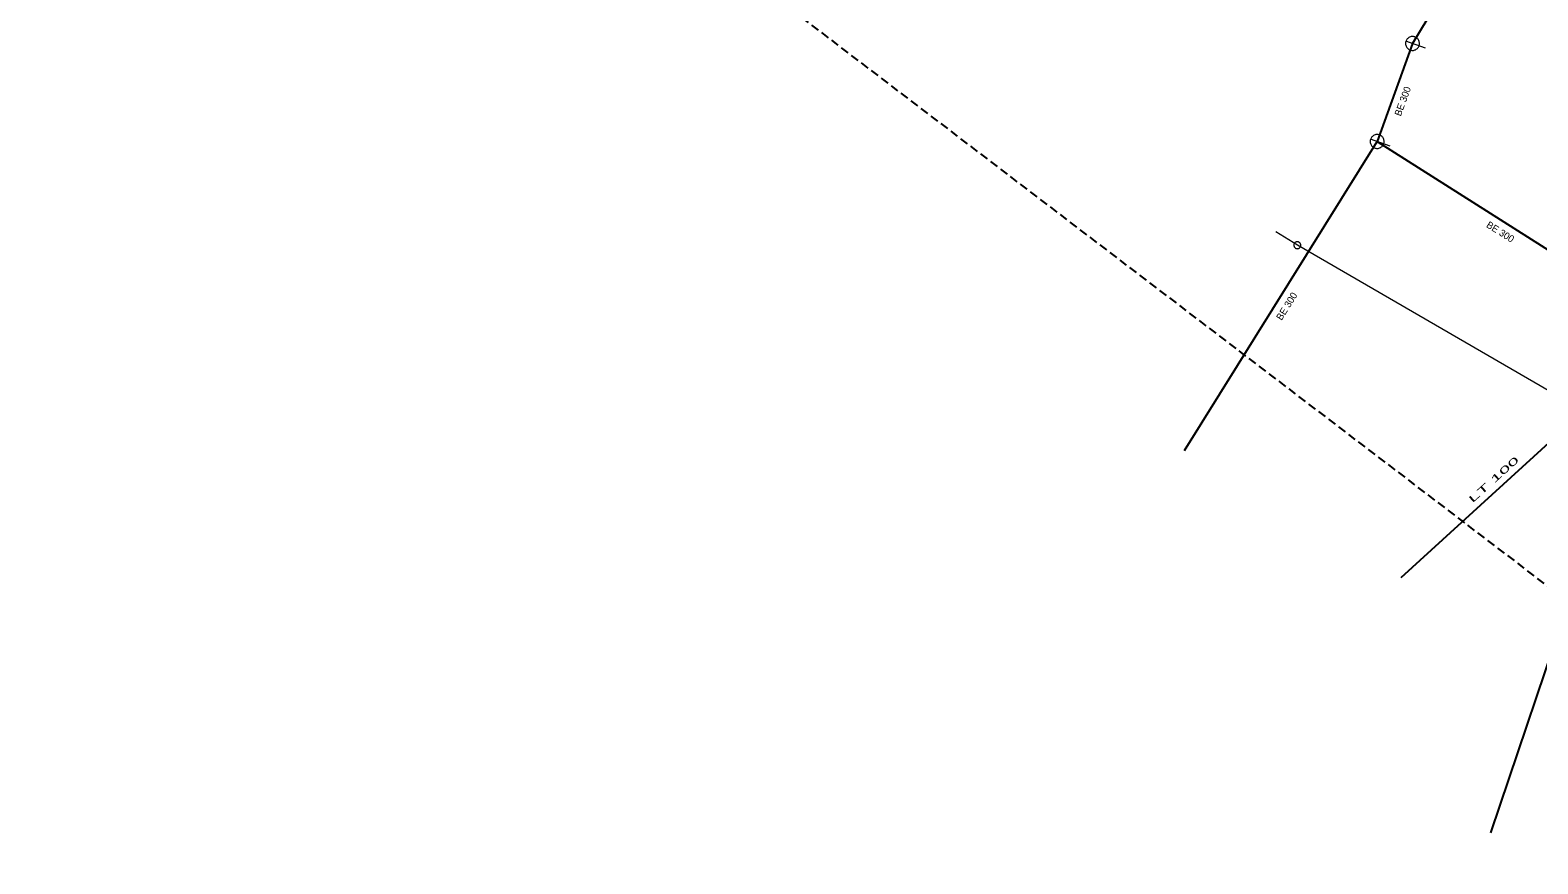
# Model space of a CAD drawing. Extents: x -791337 to -790755, y -988454 to -987923.
# Drawn here: x -791331.5 to -791114.4, y -988280.4 to -988160.4 of the extents above; entities that cross this region are included whole.
import ezdxf

# ---------------------------------------------------------------- set-up
doc = ezdxf.new("R2010")
doc.units = 0
doc.header["$LTSCALE"] = 0.4
doc.linetypes.add('MEDIUM_DASHED', pattern=[4.5, 3, -1.5])
for name, color, linetype, lineweight in [('1', 7, 'Continuous', 13), ('13', 7, 'Continuous', 13), ('14', 7, 'Continuous', 25), ('17', 7, 'Continuous', 25), ('22', 7, 'Continuous', 13), ('23', 7, 'Continuous', 13), ('63', 7, 'MEDIUM_DASHED', 25)]:
    doc.layers.add(name, color=color, linetype=linetype, lineweight=lineweight)

msp = doc.modelspace()

# ---------------------------------------------------------------- linework, layer by layer
at = {"layer": '13'}
msp.add_line((-791149.015, -988191.33), (-791152.136, -988189.414), dxfattribs=at)
msp.add_lwpolyline([(-791107.868, -988215.265), (-791108.388, -988214.918), (-791149.015, -988191.33)], dxfattribs=at)
at = {"layer": '14'}
for p, q in [((-791124.854, -988149.635), (-791132.46, -988162.294)), ((-791132.46, -988162.294), (-791137.55, -988176.404)), ((-791165.269, -988220.905), (-791137.55, -988176.404)), ((-791137.55, -988176.404), (-791099.119, -988200.823)), ((-791106.431, -988231.991), (-791121.225, -988275.947))]:
    msp.add_line(p, q, dxfattribs=at)
at = {"layer": '17'}
msp.add_lwpolyline([(-791134.081, -988239.197), (-791107.868, -988215.265), (-791103.719, -988211.362), (-791100.587, -988208.045)], dxfattribs=at)
at = {"layer": '22'}
for p, q in [((-791130.578, -988162.972), (-791133.4, -988161.954)), ((-791135.668, -988177.082), (-791138.49, -988176.064))]:
    msp.add_line(p, q, dxfattribs=at)
for points in [[(-791132.12, -988161.353), (-791132.224, -988161.322), (-791132.332, -988161.302), (-791132.442, -988161.294), (-791132.55, -988161.298), (-791132.659, -988161.314), (-791132.765, -988161.341), (-791132.868, -988161.381), (-791132.964, -988161.431), (-791133.056, -988161.491), (-791133.14, -988161.561), (-791133.216, -988161.64), (-791133.283, -988161.728), (-791133.34, -988161.821), (-791133.386, -988161.92), (-791133.422, -988162.024), (-791133.445, -988162.13), (-791133.458, -988162.24), (-791133.458, -988162.349), (-791133.445, -988162.458), (-791133.422, -988162.564), (-791133.386, -988162.668), (-791133.34, -988162.767), (-791133.282, -988162.861), (-791133.216, -988162.948), (-791133.14, -988163.026), (-791133.056, -988163.096), (-791132.964, -988163.157), (-791132.867, -988163.206), (-791132.764, -988163.246), (-791132.658, -988163.273), (-791132.55, -988163.29), (-791132.441, -988163.293), (-791132.332, -988163.286), (-791132.224, -988163.266), (-791132.119, -988163.234), (-791132.019, -988163.191), (-791131.923, -988163.138), (-791131.834, -988163.074), (-791131.752, -988163.001), (-791131.679, -988162.919), (-791131.615, -988162.831), (-791131.562, -988162.735), (-791131.519, -988162.634), (-791131.487, -988162.529), (-791131.468, -988162.422), (-791131.459, -988162.313), (-791131.463, -988162.203), (-791131.479, -988162.094), (-791131.507, -988161.989), (-791131.546, -988161.886), (-791131.595, -988161.789), (-791131.656, -988161.698), (-791131.726, -988161.613), (-791131.805, -988161.538), (-791131.891, -988161.471), (-791131.985, -988161.413), (-791132.084, -988161.367)], [(-791137.21, -988175.463), (-791137.314, -988175.432), (-791137.422, -988175.412), (-791137.532, -988175.404), (-791137.64, -988175.408), (-791137.749, -988175.424), (-791137.855, -988175.451), (-791137.958, -988175.491), (-791138.054, -988175.541), (-791138.146, -988175.601), (-791138.23, -988175.671), (-791138.306, -988175.75), (-791138.373, -988175.838), (-791138.43, -988175.931), (-791138.476, -988176.03), (-791138.512, -988176.134), (-791138.535, -988176.24), (-791138.548, -988176.35), (-791138.548, -988176.459), (-791138.535, -988176.568), (-791138.512, -988176.674), (-791138.476, -988176.778), (-791138.43, -988176.877), (-791138.372, -988176.971), (-791138.306, -988177.058), (-791138.23, -988177.136), (-791138.146, -988177.206), (-791138.054, -988177.267), (-791137.957, -988177.316), (-791137.854, -988177.356), (-791137.748, -988177.383), (-791137.64, -988177.4), (-791137.531, -988177.403), (-791137.422, -988177.396), (-791137.314, -988177.376), (-791137.209, -988177.344), (-791137.109, -988177.301), (-791137.013, -988177.248), (-791136.924, -988177.184), (-791136.842, -988177.111), (-791136.769, -988177.029), (-791136.705, -988176.941), (-791136.652, -988176.845), (-791136.609, -988176.744), (-791136.577, -988176.639), (-791136.558, -988176.532), (-791136.549, -988176.423), (-791136.553, -988176.313), (-791136.569, -988176.204), (-791136.597, -988176.099), (-791136.636, -988175.996), (-791136.685, -988175.899), (-791136.746, -988175.808), (-791136.816, -988175.723), (-791136.895, -988175.648), (-791136.981, -988175.581), (-791137.075, -988175.523), (-791137.174, -988175.477)]]:
    msp.add_lwpolyline(points, close=True, dxfattribs=at)
at = {"layer": '23'}
for points in [[(-791148.609, -988191.581), (-791148.585, -988191.533), (-791148.567, -988191.484), (-791148.556, -988191.434), (-791148.548, -988191.382), (-791148.546, -988191.33), (-791148.551, -988191.277), (-791148.559, -988191.226), (-791148.574, -988191.176), (-791148.593, -988191.127), (-791148.617, -988191.081), (-791148.646, -988191.037), (-791148.681, -988190.996), (-791148.718, -988190.96), (-791148.759, -988190.929), (-791148.802, -988190.901), (-791148.851, -988190.878), (-791148.899, -988190.86), (-791148.951, -988190.847), (-791149.001, -988190.839), (-791149.054, -988190.837), (-791149.107, -988190.842), (-791149.158, -988190.851), (-791149.209, -988190.866), (-791149.258, -988190.884), (-791149.303, -988190.909), (-791149.347, -988190.939), (-791149.386, -988190.972), (-791149.423, -988191.01), (-791149.455, -988191.052), (-791149.483, -988191.095), (-791149.506, -988191.142), (-791149.524, -988191.192), (-791149.537, -988191.243), (-791149.544, -988191.294), (-791149.545, -988191.345), (-791149.542, -988191.398), (-791149.533, -988191.45), (-791149.518, -988191.501), (-791149.499, -988191.549)], [(-791148.951, -988190.847), (-791149.001, -988190.839), (-791149.054, -988190.837), (-791149.107, -988190.842), (-791149.158, -988190.851), (-791149.209, -988190.866), (-791149.258, -988190.884), (-791149.303, -988190.909), (-791149.347, -988190.939), (-791149.386, -988190.972), (-791149.423, -988191.01), (-791149.455, -988191.052), (-791149.483, -988191.095), (-791149.506, -988191.142), (-791149.524, -988191.192), (-791149.537, -988191.243), (-791149.544, -988191.294), (-791149.545, -988191.345), (-791149.542, -988191.398), (-791149.533, -988191.45), (-791149.518, -988191.501), (-791149.499, -988191.549), (-791149.475, -988191.595), (-791149.445, -988191.638), (-791149.413, -988191.679), (-791149.373, -988191.715), (-791149.333, -988191.746), (-791149.289, -988191.775), (-791149.242, -988191.797), (-791149.193, -988191.816), (-791149.141, -988191.829), (-791149.09, -988191.835), (-791149.037, -988191.838), (-791148.986, -988191.834), (-791148.934, -988191.824), (-791148.884, -988191.811), (-791148.836, -988191.791), (-791148.788, -988191.766), (-791148.745, -988191.737), (-791148.705, -988191.703)], [(-791149.499, -988191.549), (-791149.475, -988191.595), (-791149.445, -988191.638), (-791149.413, -988191.679), (-791149.373, -988191.715), (-791149.333, -988191.746), (-791149.289, -988191.775), (-791149.242, -988191.797), (-791149.193, -988191.816), (-791149.141, -988191.829), (-791149.09, -988191.835), (-791149.037, -988191.838), (-791148.986, -988191.834), (-791148.934, -988191.824), (-791148.884, -988191.811), (-791148.836, -988191.791), (-791148.788, -988191.766), (-791148.745, -988191.737), (-791148.705, -988191.703), (-791148.669, -988191.665), (-791148.637, -988191.625), (-791148.609, -988191.581), (-791148.585, -988191.533), (-791148.567, -988191.484), (-791148.556, -988191.434), (-791148.548, -988191.382), (-791148.546, -988191.33), (-791148.551, -988191.277), (-791148.559, -988191.226), (-791148.574, -988191.176), (-791148.593, -988191.127), (-791148.617, -988191.081), (-791148.646, -988191.037), (-791148.681, -988190.996), (-791148.718, -988190.96), (-791148.759, -988190.929), (-791148.802, -988190.901), (-791148.851, -988190.878), (-791148.899, -988190.86), (-791148.951, -988190.847)], [(-791148.705, -988191.703), (-791148.669, -988191.665), (-791148.637, -988191.625), (-791148.609, -988191.581)]]:
    msp.add_lwpolyline(points, dxfattribs=at)
at = {"layer": '63'}
msp.add_lwpolyline([(-791231.02, -987923.132), (-790755.118, -988202.253), (-790755.118, -988202.253), (-790903.053, -988400.429), (-790903.053, -988400.429), (-791331.504, -988073.857), (-791331.504, -988073.857)], close=True, dxfattribs=at)

# ---------------------------------------------------------------- texts
at = {"layer": '1'}
for rotation, p in [(70, (-791134.155, -988172.844)), (328, (-791121.931, -988188.68)), (58, (-791151.31, -988202.25))]:
    msp.add_text('BE 300', height=1, rotation=rotation, dxfattribs=at).set_placement(p)
at = {"layer": '1', "width": 2.2}
msp.add_text('LT 100', height=1, rotation=42, dxfattribs=at).set_placement((-791123.838, -988228.511))

doc.saveas('drawing.dxf')
